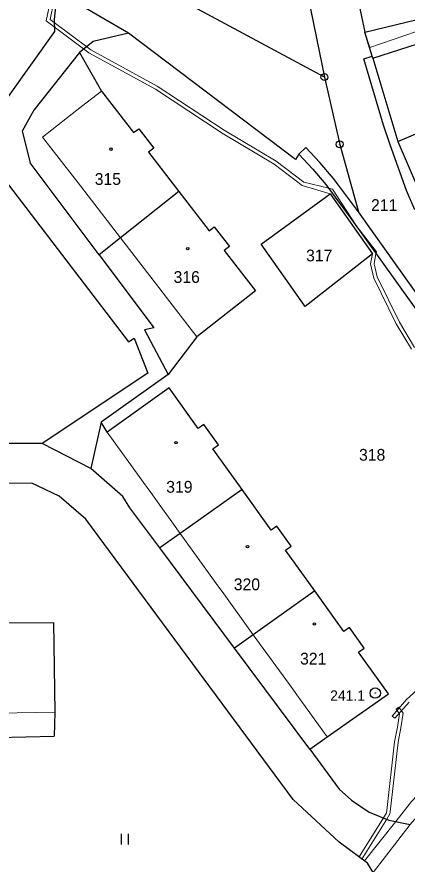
# Model space of a CAD drawing. Extents: x -727701 to -724405, y -960481 to -957284.
# Drawn here: x -726957 to -726900.7, y -958207.9 to -958085.7 of the extents above; entities that cross this region are included whole.
import ezdxf
from ezdxf.enums import TextEntityAlignment as Align

# ---------------------------------------------------------------- set-up
doc = ezdxf.new("R2010")
doc.units = 0
doc.header["$LTSCALE"] = 0.68
for name, color, linetype, lineweight in [('1', 7, 'Continuous', 25), ('13', 7, 'Continuous', 13), ('3', 7, 'Continuous', 25), ('4', 7, 'Continuous', 13), ('5', 7, 'Continuous', 25), ('8', 7, 'Continuous', 25)]:
    doc.layers.add(name, color=color, linetype=linetype, lineweight=lineweight)
doc.layers.add('2', color=7, linetype='Continuous')

msp = doc.modelspace()

# ---------------------------------------------------------------- linework, layer by layer
at = {"layer": '1'}
for p, q in [((-726918.07, -958067.64), (-726912.64, -958094.35)), ((-726911.28, -958067.44), (-726906.79, -958087.87)), ((-726951.25, -958082), (-726951.68, -958086.07)), ((-726940.93, -958088.01), (-726951.25, -958082)), ((-726906.79, -958087.87), (-726889.47, -958083.69)), ((-726912.64, -958094.35), (-726931.56, -958084.2)), ((-726951.68, -958086.07), (-726951.61, -958087.78)), ((-726951.61, -958087.78), (-726958.52, -958097.51)), ((-726905.66, -958091.62), (-726891.47, -958087.04)), ((-726940.93, -958088.01), (-726946.04, -958089.23)), ((-726916.84, -958106.27), (-726940.93, -958088.01)), ((-726905.74, -958091.36), (-726906.79, -958087.87)), ((-726946.04, -958089.23), (-726948.02, -958090.8)), ((-726948.02, -958090.8), (-726954.61, -958099.11)), ((-726948.02, -958090.8), (-726944.83, -958096.38)), ((-726906.98, -958091.71), (-726905.74, -958091.36)), ((-726905.66, -958091.62), (-726905.74, -958091.36)), ((-726904.1, -958101.29), (-726906.98, -958091.71)), ((-726905.66, -958091.62), (-726902.07, -958103.67)), ((-726912.64, -958094.35), (-726910.44, -958104.06)), ((-726944.83, -958096.38), (-726940.2, -958102.37)), ((-726954.61, -958099.11), (-726956.26, -958102.18)), ((-726956.26, -958102.18), (-726955.11, -958106.72)), ((-726940.2, -958102.37), (-726939.46, -958101.8)), ((-726939.46, -958101.8), (-726937.27, -958104.63)), ((-726903.16, -958104.13), (-726904.1, -958101.29)), ((-726902.07, -958103.67), (-726896.68, -958101.34)), ((-726902.07, -958103.67), (-726897.34, -958114.63)), ((-726937.27, -958104.63), (-726938.02, -958105.2)), ((-726915.34, -958104.51), (-726916.33, -958105.47)), ((-726913.3, -958106.7), (-726915.34, -958104.51)), ((-726910.44, -958104.06), (-726907.75, -958113.81)), ((-726900.79, -958110.74), (-726903.16, -958104.13)), ((-726938.02, -958105.2), (-726933.66, -958110.86)), ((-726916.33, -958105.47), (-726916.84, -958106.27)), ((-726916.33, -958105.47), (-726914.33, -958107.66)), ((-726945.16, -958119.99), (-726955.11, -958106.72)), ((-726911.34, -958108.98), (-726913.3, -958106.7)), ((-726914.33, -958107.66), (-726912.42, -958109.87)), ((-726907.75, -958113.81), (-726911.34, -958108.98)), ((-726958.25, -958109.88), (-726940.92, -958132.54)), ((-726933.66, -958110.86), (-726942.09, -958117.56)), ((-726933.66, -958110.86), (-726929.29, -958116.52)), ((-726912.42, -958109.87), (-726908.91, -958114.63)), ((-726899.61, -958113.49), (-726900.79, -958110.74)), ((-726921.79, -958118.44), (-726911.84, -958111.2)), ((-726911.84, -958111.2), (-726905.69, -958119.88)), ((-726908.91, -958114.63), (-726880.41, -958154.56)), ((-726881.62, -958150.46), (-726907.75, -958113.81)), ((-726929.29, -958116.52), (-726928.55, -958115.94)), ((-726928.55, -958115.94), (-726926.35, -958118.79)), ((-726942.09, -958117.56), (-726945.16, -958119.99)), ((-726926.35, -958118.79), (-726927.1, -958119.36)), ((-726927.1, -958119.36), (-726922.61, -958125.18)), ((-726915.41, -958127.46), (-726921.79, -958118.44)), ((-726945.16, -958119.99), (-726937.25, -958130.53)), ((-726905.69, -958119.88), (-726915.41, -958127.46)), ((-726922.61, -958125.18), (-726931.06, -958131.82)), ((-726937.25, -958130.53), (-726938.62, -958130.83)), ((-726938.62, -958130.83), (-726935.21, -958137.28)), ((-726940.92, -958132.54), (-726940.12, -958132.01)), ((-726940.12, -958132.01), (-726938.16, -958137.09)), ((-726931.06, -958131.82), (-726935.21, -958137.28)), ((-726938.16, -958137.09), (-726953.37, -958147.23)), ((-726935.21, -958137.28), (-726944.87, -958144.15)), ((-726935.05, -958139.21), (-726943.99, -958145.61)), ((-726930.85, -958145.06), (-726935.05, -958139.21)), ((-726944.87, -958144.15), (-726946.35, -958150.83)), ((-726943.99, -958145.61), (-726944.87, -958144.15)), ((-726930.04, -958144.48), (-726930.85, -958145.06)), ((-726927.93, -958147.42), (-726930.04, -958144.48)), ((-726953.37, -958147.23), (-726971.39, -958147.18)), ((-726946.35, -958150.83), (-726953.37, -958147.23)), ((-726928.74, -958148), (-726927.93, -958147.42)), ((-726924.54, -958153.86), (-726928.74, -958148)), ((-726941.75, -958154.85), (-726946.35, -958150.83)), ((-726954.87, -958152.95), (-726966.77, -958153)), ((-726950.93, -958154.8), (-726954.87, -958152.95)), ((-726947.1, -958158.12), (-726950.93, -958154.8)), ((-726940.73, -958156.49), (-726941.75, -958154.85)), ((-726924.54, -958153.86), (-726933.46, -958160.2)), ((-726920.34, -958159.72), (-726924.54, -958153.86)), ((-726936.4, -958162.3), (-726940.73, -958156.49)), ((-726917.14, -958198.59), (-726947.1, -958158.12)), ((-726919.52, -958159.14), (-726920.34, -958159.72)), ((-726917.44, -958162.04), (-726919.52, -958159.14)), ((-726933.46, -958160.2), (-726936.4, -958162.3)), ((-726925.63, -958176.74), (-726936.4, -958162.3)), ((-726918.25, -958162.62), (-726917.44, -958162.04)), ((-726914.04, -958168.5), (-726918.25, -958162.62)), ((-726914.04, -958168.5), (-726922.91, -958174.81)), ((-726909.82, -958174.37), (-726914.04, -958168.5)), ((-726969.96, -958173.13), (-726951.75, -958173.03)), ((-726951.75, -958173.03), (-726951.57, -958186.01)), ((-726909.01, -958173.79), (-726909.82, -958174.37)), ((-726906.9, -958176.73), (-726909.01, -958173.79)), ((-726922.91, -958174.81), (-726925.63, -958176.74)), ((-726914.75, -958191.32), (-726925.63, -958176.74)), ((-726907.71, -958177.31), (-726906.9, -958176.73)), ((-726903.4, -958183.33), (-726907.71, -958177.31)), ((-726912.26, -958189.56), (-726903.4, -958183.33)), ((-726951.57, -958186.01), (-726951.68, -958189.46)), ((-726977.16, -958190.1), (-726951.68, -958189.46)), ((-726914.75, -958191.32), (-726912.26, -958189.56)), ((-726914.75, -958191.32), (-726910.5, -958197.08)), ((-726910.5, -958197.08), (-726908.73, -958198.66)), ((-726910.52, -958204.74), (-726917.14, -958198.59)), ((-726908.73, -958198.66), (-726906.19, -958200.41)), ((-726906.19, -958200.41), (-726903.34, -958201.55)), ((-726903.34, -958201.55), (-726900.26, -958202.2)), ((-726906.42, -958207.78), (-726910.52, -958204.74)), ((-726903.79, -958212.02), (-726906.42, -958207.78))]:
    msp.add_line(p, q, dxfattribs=at)
at = {"layer": '13'}
for points in [[(-726881.32, -958083.06), (-726889.47, -958083.69), (-726906.79, -958087.87), (-726906.11, -958090.11), (-726895.99, -958086.64), (-726888.66, -958085.1), (-726881.81, -958084.9), (-726870.2, -958085.53), (-726866.28, -958086.13), (-726866.49, -958087.81), (-726865.02, -958087.99), (-726864.47, -958087.79), (-726864.2, -958085.58), (-726864.93, -958084.62), (-726865.48, -958084.56), (-726869.32, -958083.69), (-726877.28, -958083.06), (-726878.58, -958082.9)], [(-726902.3, -958185.57), (-726901.82, -958186.25), (-726902.1, -958188.15), (-726902.52, -958190.25), (-726903.63, -958200.17), (-726903.67, -958200.5), (-726904.13, -958201.24), (-726907.63, -958206.88), (-726907.23, -958207.18), (-726903.65, -958201.42), (-726903.18, -958200.66), (-726903.15, -958200.38), (-726902.02, -958190.32), (-726901.6, -958188.23), (-726901.29, -958186.12), (-726901.89, -958185.28)], [(-726889.41, -958188.3), (-726892.58, -958190.92), (-726900.07, -958198.86), (-726902.35, -958201.76), (-726906.85, -958207.46), (-726906.42, -958207.78), (-726905.6, -958209.1), (-726900.26, -958202.2), (-726899.04, -958200.75), (-726898.56, -958200.17), (-726891.21, -958192.38), (-726888.45, -958190.09), (-726886.78, -958189.59), (-726884.37, -958191.53), (-726883.09, -958189.99), (-726886.36, -958187.37)]]:
    msp.add_lwpolyline(points, close=True, dxfattribs=at)
for points in [[(-726952.19, -958083.33), (-726952.81, -958086.26), (-726946.66, -958090.86), (-726937.05, -958096.08), (-726927.4, -958102.43), (-726919.88, -958106.92), (-726915.85, -958109.98), (-726911.84, -958111.2), (-726905.69, -958119.88), (-726906, -958121.32), (-726905.5, -958123.38), (-726902.27, -958129.97), (-726900.07, -958133.61)], [(-726899.65, -958133.35), (-726901.83, -958129.73), (-726905.02, -958123.2), (-726905.48, -958121.3), (-726905.2, -958119.83), (-726905.15, -958119.58), (-726907.97, -958115.9), (-726911.5, -958110.53), (-726912.03, -958110.4), (-726915.63, -958109.52), (-726919.6, -958106.5), (-726927.14, -958102.01), (-726936.79, -958095.66), (-726946.38, -958090.44), (-726952.25, -958086.06), (-726951.71, -958083.43)], [(-726894.5, -958178.46), (-726900.78, -958184.16), (-726902.85, -958186.54), (-726902.47, -958186.86), (-726900.42, -958184.52)]]:
    msp.add_lwpolyline(points, dxfattribs=at)
at = {"layer": '3'}
for p, q in [((-726941.951, -958205.06), (-726941.951, -958203.56)), ((-726940.95, -958205.06), (-726940.95, -958203.56))]:
    msp.add_line(p, q, dxfattribs=at)
at = {"layer": '4'}
for p, q in [((-726947.69, -958098.61), (-726944.83, -958096.38)), ((-726953.34, -958103.01), (-726947.69, -958098.61)), ((-726947.88, -958110.06), (-726953.34, -958103.01)), ((-726946.77, -958111.5), (-726947.88, -958110.06)), ((-726942.09, -958117.56), (-726946.77, -958111.5)), ((-726936.55, -958124.71), (-726942.09, -958117.56)), ((-726935.44, -958126.15), (-726936.55, -958124.71)), ((-726931.06, -958131.82), (-726935.44, -958126.15)), ((-726938.78, -958152.83), (-726943.99, -958145.61)), ((-726937.71, -958154.31), (-726938.78, -958152.83)), ((-726933.46, -958160.2), (-726937.71, -958154.31)), ((-726928.25, -958167.41), (-726933.46, -958160.2)), ((-726927.19, -958168.89), (-726928.25, -958167.41)), ((-726922.91, -958174.81), (-726927.19, -958168.89)), ((-726917.71, -958182.01), (-726922.91, -958174.81)), ((-726916.65, -958183.49), (-726917.71, -958182.01)), ((-726912.26, -958189.56), (-726916.65, -958183.49)), ((-726969.88, -958186.28), (-726951.57, -958186.01))]:
    msp.add_line(p, q, dxfattribs=at)
at = {"layer": '5'}
for centre in [(-726943.4668, -958104.7592), (-726932.3668, -958119.1292), (-726934.0568, -958147.0992), (-726923.7468, -958162.0992), (-726914.1068, -958173.2592)]:
    msp.add_circle(centre, 0.175, dxfattribs=at)
at = {"layer": '8'}
for centre, radius in [((-726912.64, -958094.3499), 0.5), ((-726912.64, -958094.3499), 0.0303), ((-726910.44, -958104.0599), 0.5), ((-726910.44, -958104.0599), 0.0303), ((-726905.3, -958183.2298), 0.75), ((-726905.3, -958183.2298), 0.03)]:
    msp.add_circle(centre, radius, dxfattribs=at)

# ---------------------------------------------------------------- texts
at = {"layer": '2'}
for s, p in [('315', (-726945.8, -958109.915)), ('317', (-726915.29, -958120.945)), ('316', (-726934.42, -958124.055)), ('318', (-726907.65, -958149.705)), ('319', (-726935.48, -958154.325)), ('320', (-726925.73, -958168.395)), ('321', (-726916.16, -958179.115))]:
    msp.add_text(s, height=1.7, dxfattribs=at).set_placement(p)
msp.add_text('211', height=1.7, dxfattribs=at).set_placement((-726904.019, -958113.675), align=Align.CENTER)
at = {"layer": '8'}
msp.add_text('241.1', height=1.5, dxfattribs=at).set_placement((-726906.799, -958184.347), align=Align.RIGHT)

doc.saveas('drawing.dxf')
